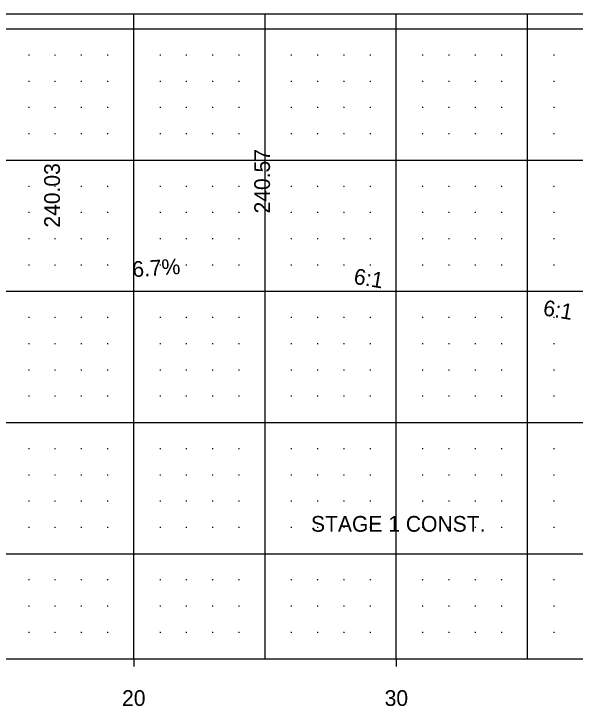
# Model space of a CAD drawing. Extents: x -80 to 80, y 222 to 253.
# Drawn here: x 15.43 to 36.81, y 224.19 to 250.57 of the extents above; entities that cross this region are included whole.
import ezdxf

# ---------------------------------------------------------------- set-up
doc = ezdxf.new("R2010")
doc.units = 0
for name, color, linetype in [('Default', 7, 'Continuous'), ('DSN_DRFT_XS Border Grid', 7, 'Continuous'), ('DSN_DRFT_XS Grid Annotations', 7, 'Continuous'), ('DSN_DRFT_XS Grid Major', 7, 'Continuous'), ('DSN_DRFT_XS Grid Minor', 7, 'Continuous'), ('DSN_RDWY_XS Annotation', 7, 'Continuous')]:
    doc.layers.add(name, color=color, linetype=linetype)

msp = doc.modelspace()

# ---------------------------------------------------------------- linework, layer by layer
at = {"layer": 'DSN_DRFT_XS Border Grid'}
for p, q in [((-77.5, 250.573), (77.5, 250.573)), ((-77.5, 226), (77.5, 226))]:
    msp.add_line(p, q, dxfattribs=at)
at = {"layer": 'DSN_DRFT_XS Grid Major'}
for p, q in [((20, 226), (20, 250.573)), ((25, 226), (25, 250.573)), ((30, 226), (30, 250.573)), ((35, 226), (35, 250.573)), ((-77.5, 250), (77.5, 250)), ((-77.5, 245), (77.5, 245)), ((-77.5, 240), (77.5, 240)), ((-77.5, 235), (77.5, 235)), ((-77.5, 230), (77.5, 230)), ((20, 226), (20, 225.7)), ((30, 226), (30, 225.7))]:
    msp.add_line(p, q, dxfattribs=at)
at = {"layer": 'DSN_DRFT_XS Grid Minor'}
for p, q in [((16.012, 249), (15.988, 249)), ((16, 249.012), (16, 248.988)), ((17.012, 249), (16.988, 249)), ((17, 249.012), (17, 248.988)), ((18.012, 249), (17.988, 249)), ((18, 249.012), (18, 248.988)), ((19.012, 249), (18.988, 249)), ((19, 249.012), (19, 248.988)), ((21.012, 249), (20.988, 249)), ((21, 249.012), (21, 248.988)), ((22.012, 249), (21.988, 249)), ((22, 249.012), (22, 248.988)), ((23.012, 249), (22.988, 249)), ((23, 249.012), (23, 248.988)), ((24.012, 249), (23.988, 249)), ((24, 249.012), (24, 248.988)), ((26.012, 249), (25.988, 249)), ((26, 249.012), (26, 248.988)), ((27.012, 249), (26.988, 249)), ((27, 249.012), (27, 248.988)), ((28.012, 249), (27.988, 249)), ((28, 249.012), (28, 248.988)), ((29.012, 249), (28.988, 249)), ((29, 249.012), (29, 248.988)), ((31.012, 249), (30.988, 249)), ((31, 249.012), (31, 248.988)), ((32.012, 249), (31.988, 249)), ((32, 249.012), (32, 248.988)), ((33.012, 249), (32.988, 249)), ((33, 249.012), (33, 248.988)), ((34.012, 249), (33.988, 249)), ((34, 249.012), (34, 248.988)), ((36.012, 249), (35.988, 249)), ((36, 249.012), (36, 248.988)), ((16.012, 248), (15.988, 248)), ((16, 248.012), (16, 247.988)), ((17.012, 248), (16.988, 248)), ((17, 248.012), (17, 247.988)), ((18.012, 248), (17.988, 248)), ((18, 248.012), (18, 247.988)), ((19.012, 248), (18.988, 248)), ((19, 248.012), (19, 247.988)), ((21.012, 248), (20.988, 248)), ((21, 248.012), (21, 247.988)), ((22.012, 248), (21.988, 248)), ((22, 248.012), (22, 247.988)), ((23.012, 248), (22.988, 248)), ((23, 248.012), (23, 247.988)), ((24.012, 248), (23.988, 248)), ((24, 248.012), (24, 247.988)), ((26.012, 248), (25.988, 248)), ((26, 248.012), (26, 247.988)), ((27.012, 248), (26.988, 248)), ((27, 248.012), (27, 247.988)), ((28.012, 248), (27.988, 248)), ((28, 248.012), (28, 247.988)), ((29.012, 248), (28.988, 248)), ((29, 248.012), (29, 247.988)), ((31.012, 248), (30.988, 248)), ((31, 248.012), (31, 247.988)), ((32.012, 248), (31.988, 248)), ((32, 248.012), (32, 247.988)), ((33.012, 248), (32.988, 248)), ((33, 248.012), (33, 247.988)), ((34.012, 248), (33.988, 248)), ((34, 248.012), (34, 247.988)), ((36.012, 248), (35.988, 248)), ((36, 248.012), (36, 247.988)), ((16.012, 247), (15.988, 247)), ((16, 247.012), (16, 246.988)), ((17.012, 247), (16.988, 247)), ((17, 247.012), (17, 246.988)), ((18.012, 247), (17.988, 247)), ((18, 247.012), (18, 246.988)), ((19.012, 247), (18.988, 247)), ((19, 247.012), (19, 246.988)), ((21.012, 247), (20.988, 247)), ((21, 247.012), (21, 246.988)), ((22.012, 247), (21.988, 247)), ((22, 247.012), (22, 246.988)), ((23.012, 247), (22.988, 247)), ((23, 247.012), (23, 246.988)), ((24.012, 247), (23.988, 247)), ((24, 247.012), (24, 246.988)), ((26.012, 247), (25.988, 247)), ((26, 247.012), (26, 246.988)), ((27.012, 247), (26.988, 247)), ((27, 247.012), (27, 246.988)), ((28.012, 247), (27.988, 247)), ((28, 247.012), (28, 246.988)), ((29.012, 247), (28.988, 247)), ((29, 247.012), (29, 246.988)), ((31.012, 247), (30.988, 247)), ((31, 247.012), (31, 246.988)), ((32.012, 247), (31.988, 247)), ((32, 247.012), (32, 246.988)), ((33.012, 247), (32.988, 247)), ((33, 247.012), (33, 246.988)), ((34.012, 247), (33.988, 247)), ((34, 247.012), (34, 246.988)), ((36.012, 247), (35.988, 247)), ((36, 247.012), (36, 246.988)), ((16.012, 246), (15.988, 246)), ((16, 246.012), (16, 245.988)), ((17.012, 246), (16.988, 246)), ((17, 246.012), (17, 245.988)), ((18.012, 246), (17.988, 246)), ((18, 246.012), (18, 245.988)), ((19.012, 246), (18.988, 246)), ((19, 246.012), (19, 245.988)), ((21.012, 246), (20.988, 246)), ((21, 246.012), (21, 245.988)), ((22.012, 246), (21.988, 246)), ((22, 246.012), (22, 245.988)), ((23.012, 246), (22.988, 246)), ((23, 246.012), (23, 245.988)), ((24.012, 246), (23.988, 246)), ((24, 246.012), (24, 245.988)), ((26.012, 246), (25.988, 246)), ((26, 246.012), (26, 245.988)), ((27.012, 246), (26.988, 246)), ((27, 246.012), (27, 245.988)), ((28.012, 246), (27.988, 246)), ((28, 246.012), (28, 245.988)), ((29.012, 246), (28.988, 246)), ((29, 246.012), (29, 245.988)), ((31.012, 246), (30.988, 246)), ((31, 246.012), (31, 245.988)), ((32.012, 246), (31.988, 246)), ((32, 246.012), (32, 245.988)), ((33.012, 246), (32.988, 246)), ((33, 246.012), (33, 245.988)), ((34.012, 246), (33.988, 246)), ((34, 246.012), (34, 245.988)), ((36.012, 246), (35.988, 246)), ((36, 246.012), (36, 245.988)), ((16.012, 244), (15.988, 244)), ((16, 244.012), (16, 243.988)), ((17.012, 244), (16.988, 244)), ((17, 244.012), (17, 243.988)), ((18.012, 244), (17.988, 244)), ((18, 244.012), (18, 243.988)), ((19.012, 244), (18.988, 244)), ((19, 244.012), (19, 243.988)), ((21.012, 244), (20.988, 244)), ((21, 244.012), (21, 243.988)), ((22.012, 244), (21.988, 244)), ((22, 244.012), (22, 243.988)), ((23.012, 244), (22.988, 244)), ((23, 244.012), (23, 243.988)), ((24.012, 244), (23.988, 244)), ((24, 244.012), (24, 243.988)), ((26.012, 244), (25.988, 244)), ((26, 244.012), (26, 243.988)), ((27.012, 244), (26.988, 244)), ((27, 244.012), (27, 243.988)), ((28.012, 244), (27.988, 244)), ((28, 244.012), (28, 243.988)), ((29.012, 244), (28.988, 244)), ((29, 244.012), (29, 243.988)), ((31.012, 244), (30.988, 244)), ((31, 244.012), (31, 243.988)), ((32.012, 244), (31.988, 244)), ((32, 244.012), (32, 243.988)), ((33.012, 244), (32.988, 244)), ((33, 244.012), (33, 243.988)), ((34.012, 244), (33.988, 244)), ((34, 244.012), (34, 243.988)), ((36.012, 244), (35.988, 244)), ((36, 244.012), (36, 243.988)), ((16.012, 243), (15.988, 243)), ((16, 243.012), (16, 242.988)), ((17.012, 243), (16.988, 243)), ((17, 243.012), (17, 242.988)), ((18.012, 243), (17.988, 243)), ((18, 243.012), (18, 242.988)), ((19.012, 243), (18.988, 243)), ((19, 243.012), (19, 242.988)), ((21.012, 243), (20.988, 243)), ((21, 243.012), (21, 242.988)), ((22.012, 243), (21.988, 243)), ((22, 243.012), (22, 242.988)), ((23.012, 243), (22.988, 243)), ((23, 243.012), (23, 242.988)), ((24.012, 243), (23.988, 243)), ((24, 243.012), (24, 242.988)), ((26.012, 243), (25.988, 243)), ((26, 243.012), (26, 242.988)), ((27.012, 243), (26.988, 243)), ((27, 243.012), (27, 242.988)), ((28.012, 243), (27.988, 243)), ((28, 243.012), (28, 242.988)), ((29.012, 243), (28.988, 243)), ((29, 243.012), (29, 242.988)), ((31.012, 243), (30.988, 243)), ((31, 243.012), (31, 242.988)), ((32.012, 243), (31.988, 243)), ((32, 243.012), (32, 242.988)), ((33.012, 243), (32.988, 243)), ((33, 243.012), (33, 242.988)), ((34.012, 243), (33.988, 243)), ((34, 243.012), (34, 242.988)), ((36.012, 243), (35.988, 243)), ((36, 243.012), (36, 242.988)), ((16.012, 242), (15.988, 242)), ((16, 242.012), (16, 241.988)), ((17.012, 242), (16.988, 242)), ((17, 242.012), (17, 241.988)), ((18.012, 242), (17.988, 242)), ((18, 242.012), (18, 241.988)), ((19.012, 242), (18.988, 242)), ((19, 242.012), (19, 241.988)), ((21.012, 242), (20.988, 242)), ((21, 242.012), (21, 241.988)), ((22.012, 242), (21.988, 242)), ((22, 242.012), (22, 241.988)), ((23.012, 242), (22.988, 242)), ((23, 242.012), (23, 241.988)), ((24.012, 242), (23.988, 242)), ((24, 242.012), (24, 241.988)), ((26.012, 242), (25.988, 242)), ((26, 242.012), (26, 241.988)), ((27.012, 242), (26.988, 242)), ((27, 242.012), (27, 241.988)), ((28.012, 242), (27.988, 242)), ((28, 242.012), (28, 241.988)), ((29.012, 242), (28.988, 242)), ((29, 242.012), (29, 241.988)), ((31.012, 242), (30.988, 242)), ((31, 242.012), (31, 241.988)), ((32.012, 242), (31.988, 242)), ((32, 242.012), (32, 241.988)), ((33.012, 242), (32.988, 242)), ((33, 242.012), (33, 241.988)), ((34.012, 242), (33.988, 242)), ((34, 242.012), (34, 241.988)), ((36.012, 242), (35.988, 242)), ((36, 242.012), (36, 241.988)), ((16.012, 241), (15.988, 241)), ((16, 241.012), (16, 240.988)), ((17.012, 241), (16.988, 241)), ((17, 241.012), (17, 240.988)), ((18.012, 241), (17.988, 241)), ((18, 241.012), (18, 240.988)), ((19.012, 241), (18.988, 241)), ((19, 241.012), (19, 240.988)), ((21.012, 241), (20.988, 241)), ((21, 241.012), (21, 240.988)), ((22.012, 241), (21.988, 241)), ((22, 241.012), (22, 240.988)), ((23.012, 241), (22.988, 241)), ((23, 241.012), (23, 240.988)), ((24.012, 241), (23.988, 241)), ((24, 241.012), (24, 240.988)), ((26.012, 241), (25.988, 241)), ((26, 241.012), (26, 240.988)), ((27.012, 241), (26.988, 241)), ((27, 241.012), (27, 240.988)), ((28.012, 241), (27.988, 241)), ((28, 241.012), (28, 240.988)), ((29.012, 241), (28.988, 241)), ((29, 241.012), (29, 240.988)), ((31.012, 241), (30.988, 241)), ((31, 241.012), (31, 240.988)), ((32.012, 241), (31.988, 241)), ((32, 241.012), (32, 240.988)), ((33.012, 241), (32.988, 241)), ((33, 241.012), (33, 240.988)), ((34.012, 241), (33.988, 241)), ((34, 241.012), (34, 240.988)), ((36.012, 241), (35.988, 241)), ((36, 241.012), (36, 240.988)), ((16.012, 239), (15.988, 239)), ((16, 239.012), (16, 238.988)), ((17.012, 239), (16.988, 239)), ((17, 239.012), (17, 238.988)), ((18.012, 239), (17.988, 239)), ((18, 239.012), (18, 238.988)), ((19.012, 239), (18.988, 239)), ((19, 239.012), (19, 238.988)), ((21.012, 239), (20.988, 239)), ((21, 239.012), (21, 238.988)), ((22.012, 239), (21.988, 239)), ((22, 239.012), (22, 238.988)), ((23.012, 239), (22.988, 239)), ((23, 239.012), (23, 238.988)), ((24.012, 239), (23.988, 239)), ((24, 239.012), (24, 238.988)), ((26.012, 239), (25.988, 239)), ((26, 239.012), (26, 238.988)), ((27.012, 239), (26.988, 239)), ((27, 239.012), (27, 238.988)), ((28.012, 239), (27.988, 239)), ((28, 239.012), (28, 238.988)), ((29.012, 239), (28.988, 239)), ((29, 239.012), (29, 238.988)), ((31.012, 239), (30.988, 239)), ((31, 239.012), (31, 238.988)), ((32.012, 239), (31.988, 239)), ((32, 239.012), (32, 238.988)), ((33.012, 239), (32.988, 239)), ((33, 239.012), (33, 238.988)), ((34.012, 239), (33.988, 239)), ((34, 239.012), (34, 238.988)), ((36.012, 239), (35.988, 239)), ((36, 239.012), (36, 238.988)), ((16.012, 238), (15.988, 238)), ((16, 238.012), (16, 237.988)), ((17.012, 238), (16.988, 238)), ((17, 238.012), (17, 237.988)), ((18.012, 238), (17.988, 238)), ((18, 238.012), (18, 237.988)), ((19.012, 238), (18.988, 238)), ((19, 238.012), (19, 237.988)), ((21.012, 238), (20.988, 238)), ((21, 238.012), (21, 237.988)), ((22.012, 238), (21.988, 238)), ((22, 238.012), (22, 237.988)), ((23.012, 238), (22.988, 238)), ((23, 238.012), (23, 237.988)), ((24.012, 238), (23.988, 238)), ((24, 238.012), (24, 237.988)), ((26.012, 238), (25.988, 238)), ((26, 238.012), (26, 237.988)), ((27.012, 238), (26.988, 238)), ((27, 238.012), (27, 237.988)), ((28.012, 238), (27.988, 238)), ((28, 238.012), (28, 237.988)), ((29.012, 238), (28.988, 238)), ((29, 238.012), (29, 237.988)), ((31.012, 238), (30.988, 238)), ((31, 238.012), (31, 237.988)), ((32.012, 238), (31.988, 238)), ((32, 238.012), (32, 237.988)), ((33.012, 238), (32.988, 238)), ((33, 238.012), (33, 237.988)), ((34.012, 238), (33.988, 238)), ((34, 238.012), (34, 237.988)), ((36.012, 238), (35.988, 238)), ((36, 238.012), (36, 237.988)), ((16.012, 237), (15.988, 237)), ((16, 237.012), (16, 236.988)), ((17.012, 237), (16.988, 237)), ((17, 237.012), (17, 236.988)), ((18.012, 237), (17.988, 237)), ((18, 237.012), (18, 236.988)), ((19.012, 237), (18.988, 237)), ((19, 237.012), (19, 236.988)), ((21.012, 237), (20.988, 237)), ((21, 237.012), (21, 236.988)), ((22.012, 237), (21.988, 237)), ((22, 237.012), (22, 236.988)), ((23.012, 237), (22.988, 237)), ((23, 237.012), (23, 236.988)), ((24.012, 237), (23.988, 237)), ((24, 237.012), (24, 236.988)), ((26.012, 237), (25.988, 237)), ((26, 237.012), (26, 236.988)), ((27.012, 237), (26.988, 237)), ((27, 237.012), (27, 236.988)), ((28.012, 237), (27.988, 237)), ((28, 237.012), (28, 236.988)), ((29.012, 237), (28.988, 237)), ((29, 237.012), (29, 236.988)), ((31.012, 237), (30.988, 237)), ((31, 237.012), (31, 236.988)), ((32.012, 237), (31.988, 237)), ((32, 237.012), (32, 236.988)), ((33.012, 237), (32.988, 237)), ((33, 237.012), (33, 236.988)), ((34.012, 237), (33.988, 237)), ((34, 237.012), (34, 236.988)), ((36.012, 237), (35.988, 237)), ((36, 237.012), (36, 236.988)), ((16.012, 236), (15.988, 236)), ((16, 236.012), (16, 235.988)), ((17.012, 236), (16.988, 236)), ((17, 236.012), (17, 235.988)), ((18.012, 236), (17.988, 236)), ((18, 236.012), (18, 235.988)), ((19.012, 236), (18.988, 236)), ((19, 236.012), (19, 235.988)), ((21.012, 236), (20.988, 236)), ((21, 236.012), (21, 235.988)), ((22.012, 236), (21.988, 236)), ((22, 236.012), (22, 235.988)), ((23.012, 236), (22.988, 236)), ((23, 236.012), (23, 235.988)), ((24.012, 236), (23.988, 236)), ((24, 236.012), (24, 235.988)), ((26.012, 236), (25.988, 236)), ((26, 236.012), (26, 235.988)), ((27.012, 236), (26.988, 236)), ((27, 236.012), (27, 235.988)), ((28.012, 236), (27.988, 236)), ((28, 236.012), (28, 235.988)), ((29.012, 236), (28.988, 236)), ((29, 236.012), (29, 235.988)), ((31.012, 236), (30.988, 236)), ((31, 236.012), (31, 235.988)), ((32.012, 236), (31.988, 236)), ((32, 236.012), (32, 235.988)), ((33.012, 236), (32.988, 236)), ((33, 236.012), (33, 235.988)), ((34.012, 236), (33.988, 236)), ((34, 236.012), (34, 235.988)), ((36.012, 236), (35.988, 236)), ((36, 236.012), (36, 235.988)), ((16, 234.012), (16, 233.988)), ((17, 234.012), (17, 233.988)), ((18, 234.012), (18, 233.988)), ((19, 234.012), (19, 233.988)), ((21, 234.012), (21, 233.988)), ((22, 234.012), (22, 233.988)), ((23, 234.012), (23, 233.988)), ((24, 234.012), (24, 233.988)), ((26, 234.012), (26, 233.988)), ((27, 234.012), (27, 233.988)), ((28, 234.012), (28, 233.988)), ((29, 234.012), (29, 233.988)), ((31, 234.012), (31, 233.988)), ((32, 234.012), (32, 233.988)), ((33, 234.012), (33, 233.988)), ((34, 234.012), (34, 233.988)), ((36, 234.012), (36, 233.988)), ((16.012, 234), (15.988, 234)), ((17.012, 234), (16.988, 234)), ((18.012, 234), (17.988, 234)), ((19.012, 234), (18.988, 234)), ((21.012, 234), (20.988, 234)), ((22.012, 234), (21.988, 234)), ((23.012, 234), (22.988, 234)), ((24.012, 234), (23.988, 234)), ((26.012, 234), (25.988, 234)), ((27.012, 234), (26.988, 234)), ((28.012, 234), (27.988, 234)), ((29.012, 234), (28.988, 234)), ((31.012, 234), (30.988, 234)), ((32.012, 234), (31.988, 234)), ((33.012, 234), (32.988, 234)), ((34.012, 234), (33.988, 234)), ((36.012, 234), (35.988, 234)), ((16.012, 233), (15.988, 233)), ((16, 233.012), (16, 232.988)), ((17.012, 233), (16.988, 233)), ((17, 233.012), (17, 232.988)), ((18.012, 233), (17.988, 233)), ((18, 233.012), (18, 232.988)), ((19.012, 233), (18.988, 233)), ((19, 233.012), (19, 232.988)), ((21.012, 233), (20.988, 233)), ((21, 233.012), (21, 232.988)), ((22.012, 233), (21.988, 233)), ((22, 233.012), (22, 232.988)), ((23.012, 233), (22.988, 233)), ((23, 233.012), (23, 232.988)), ((24.012, 233), (23.988, 233)), ((24, 233.012), (24, 232.988)), ((26.012, 233), (25.988, 233)), ((26, 233.012), (26, 232.988)), ((27.012, 233), (26.988, 233)), ((27, 233.012), (27, 232.988)), ((28.012, 233), (27.988, 233)), ((28, 233.012), (28, 232.988)), ((29.012, 233), (28.988, 233)), ((29, 233.012), (29, 232.988)), ((31.012, 233), (30.988, 233)), ((31, 233.012), (31, 232.988)), ((32.012, 233), (31.988, 233)), ((32, 233.012), (32, 232.988)), ((33.012, 233), (32.988, 233)), ((33, 233.012), (33, 232.988)), ((34.012, 233), (33.988, 233)), ((34, 233.012), (34, 232.988)), ((36.012, 233), (35.988, 233)), ((36, 233.012), (36, 232.988)), ((16.012, 232), (15.988, 232)), ((16, 232.012), (16, 231.988)), ((17.012, 232), (16.988, 232)), ((17, 232.012), (17, 231.988)), ((18.012, 232), (17.988, 232)), ((18, 232.012), (18, 231.988)), ((19.012, 232), (18.988, 232)), ((19, 232.012), (19, 231.988)), ((21.012, 232), (20.988, 232)), ((21, 232.012), (21, 231.988)), ((22.012, 232), (21.988, 232)), ((22, 232.012), (22, 231.988)), ((23.012, 232), (22.988, 232)), ((23, 232.012), (23, 231.988)), ((24.012, 232), (23.988, 232)), ((24, 232.012), (24, 231.988)), ((26.012, 232), (25.988, 232)), ((26, 232.012), (26, 231.988)), ((27.012, 232), (26.988, 232)), ((27, 232.012), (27, 231.988)), ((28.012, 232), (27.988, 232)), ((28, 232.012), (28, 231.988)), ((29.012, 232), (28.988, 232)), ((29, 232.012), (29, 231.988)), ((31.012, 232), (30.988, 232)), ((31, 232.012), (31, 231.988)), ((32.012, 232), (31.988, 232)), ((32, 232.012), (32, 231.988)), ((33.012, 232), (32.988, 232)), ((33, 232.012), (33, 231.988)), ((34.012, 232), (33.988, 232)), ((34, 232.012), (34, 231.988)), ((36.012, 232), (35.988, 232)), ((36, 232.012), (36, 231.988)), ((16.012, 231), (15.988, 231)), ((16, 231.012), (16, 230.988)), ((17.012, 231), (16.988, 231)), ((17, 231.012), (17, 230.988)), ((18.012, 231), (17.988, 231)), ((18, 231.012), (18, 230.988)), ((19.012, 231), (18.988, 231)), ((19, 231.012), (19, 230.988)), ((21.012, 231), (20.988, 231)), ((21, 231.012), (21, 230.988)), ((22.012, 231), (21.988, 231)), ((22, 231.012), (22, 230.988)), ((23.012, 231), (22.988, 231)), ((23, 231.012), (23, 230.988)), ((24.012, 231), (23.988, 231)), ((24, 231.012), (24, 230.988)), ((26.012, 231), (25.988, 231)), ((26, 231.012), (26, 230.988)), ((27.012, 231), (26.988, 231)), ((27, 231.012), (27, 230.988)), ((28.012, 231), (27.988, 231)), ((28, 231.012), (28, 230.988)), ((29.012, 231), (28.988, 231)), ((29, 231.012), (29, 230.988)), ((31.012, 231), (30.988, 231)), ((31, 231.012), (31, 230.988)), ((32.012, 231), (31.988, 231)), ((32, 231.012), (32, 230.988)), ((33.012, 231), (32.988, 231)), ((33, 231.012), (33, 230.988)), ((34.012, 231), (33.988, 231)), ((34, 231.012), (34, 230.988)), ((36.012, 231), (35.988, 231)), ((36, 231.012), (36, 230.988)), ((16.012, 229), (15.988, 229)), ((16, 229.012), (16, 228.988)), ((17.012, 229), (16.988, 229)), ((17, 229.012), (17, 228.988)), ((18.012, 229), (17.988, 229)), ((18, 229.012), (18, 228.988)), ((19.012, 229), (18.988, 229)), ((19, 229.012), (19, 228.988)), ((21.012, 229), (20.988, 229)), ((21, 229.012), (21, 228.988)), ((22.012, 229), (21.988, 229)), ((22, 229.012), (22, 228.988)), ((23.012, 229), (22.988, 229)), ((23, 229.012), (23, 228.988)), ((24.012, 229), (23.988, 229)), ((24, 229.012), (24, 228.988)), ((26.012, 229), (25.988, 229)), ((26, 229.012), (26, 228.988)), ((27.012, 229), (26.988, 229)), ((27, 229.012), (27, 228.988)), ((28.012, 229), (27.988, 229)), ((28, 229.012), (28, 228.988)), ((29.012, 229), (28.988, 229)), ((29, 229.012), (29, 228.988)), ((31.012, 229), (30.988, 229)), ((31, 229.012), (31, 228.988)), ((32.012, 229), (31.988, 229)), ((32, 229.012), (32, 228.988)), ((33.012, 229), (32.988, 229)), ((33, 229.012), (33, 228.988)), ((34.012, 229), (33.988, 229)), ((34, 229.012), (34, 228.988)), ((36.012, 229), (35.988, 229)), ((36, 229.012), (36, 228.988)), ((16.012, 228), (15.988, 228)), ((16, 228.012), (16, 227.988)), ((17.012, 228), (16.988, 228)), ((17, 228.012), (17, 227.988)), ((18.012, 228), (17.988, 228)), ((18, 228.012), (18, 227.988)), ((19.012, 228), (18.988, 228)), ((19, 228.012), (19, 227.988)), ((21.012, 228), (20.988, 228)), ((21, 228.012), (21, 227.988)), ((22.012, 228), (21.988, 228)), ((22, 228.012), (22, 227.988)), ((23.012, 228), (22.988, 228)), ((23, 228.012), (23, 227.988)), ((24.012, 228), (23.988, 228)), ((24, 228.012), (24, 227.988)), ((26.012, 228), (25.988, 228)), ((26, 228.012), (26, 227.988)), ((27.012, 228), (26.988, 228)), ((27, 228.012), (27, 227.988)), ((28.012, 228), (27.988, 228)), ((28, 228.012), (28, 227.988)), ((29.012, 228), (28.988, 228)), ((29, 228.012), (29, 227.988)), ((31.012, 228), (30.988, 228)), ((31, 228.012), (31, 227.988)), ((32.012, 228), (31.988, 228)), ((32, 228.012), (32, 227.988)), ((33.012, 228), (32.988, 228)), ((33, 228.012), (33, 227.988)), ((34.012, 228), (33.988, 228)), ((34, 228.012), (34, 227.988)), ((36.012, 228), (35.988, 228)), ((36, 228.012), (36, 227.988)), ((16.012, 227), (15.988, 227)), ((16, 227.012), (16, 226.988)), ((17.012, 227), (16.988, 227)), ((17, 227.012), (17, 226.988)), ((18.012, 227), (17.988, 227)), ((18, 227.012), (18, 226.988)), ((19.012, 227), (18.988, 227)), ((19, 227.012), (19, 226.988)), ((21.012, 227), (20.988, 227)), ((21, 227.012), (21, 226.988)), ((22.012, 227), (21.988, 227)), ((22, 227.012), (22, 226.988)), ((23.012, 227), (22.988, 227)), ((23, 227.012), (23, 226.988)), ((24.012, 227), (23.988, 227)), ((24, 227.012), (24, 226.988)), ((26.012, 227), (25.988, 227)), ((26, 227.012), (26, 226.988)), ((27.012, 227), (26.988, 227)), ((27, 227.012), (27, 226.988)), ((28.012, 227), (27.988, 227)), ((28, 227.012), (28, 226.988)), ((29.012, 227), (28.988, 227)), ((29, 227.012), (29, 226.988)), ((31.012, 227), (30.988, 227)), ((31, 227.012), (31, 226.988)), ((32.012, 227), (31.988, 227)), ((32, 227.012), (32, 226.988)), ((33.012, 227), (32.988, 227)), ((33, 227.012), (33, 226.988)), ((34.012, 227), (33.988, 227)), ((34, 227.012), (34, 226.988)), ((36.012, 227), (35.988, 227)), ((36, 227.012), (36, 226.988))]:
    msp.add_line(p, q, dxfattribs=at)

# ---------------------------------------------------------------- texts
at = {"layer": 'Default'}
msp.add_text('STAGE 1 CONST.', height=0.6, dxfattribs=at).set_placement((26.751, 230.838))
at = {"layer": 'DSN_DRFT_XS Grid Annotations'}
for s, p in [('20', (19.555, 224.2)), ('30', (29.555, 224.2))]:
    msp.add_text(s, height=0.6, dxfattribs=at).set_placement(p)
at = {"layer": 'DSN_RDWY_XS Annotation'}
for s, rotation, p in [('240.57', 90, (25.189, 242.967)), ('240.03', 90, (17.189, 242.428)), ('6.7%', 3.8537, (19.964, 240.536)), ('6.7%', 3.8537, (19.964, 240.536)), ('6:1', 350.5377, (28.349, 240.291)), ('6:1', 350.5377, (35.561, 239.089))]:
    msp.add_text(s, height=0.6, rotation=rotation, dxfattribs=at).set_placement(p)

doc.saveas('drawing.dxf')
